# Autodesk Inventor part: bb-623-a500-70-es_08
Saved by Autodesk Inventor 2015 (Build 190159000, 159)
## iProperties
Created: 2022-04
Part Number: bb-623-a500-70-es_08
Checked By: TraceParts S.A.
Material: Generic
Catalog Web Link: www.traceparts.com
Document SubType Name: Modeling
Designer: TraceParts
Density: 1 g/cm^3
Appearance: Default
Company: TraceParts S.A.
Author: TraceParts
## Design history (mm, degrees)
feature "bb-623-a500-70-es_08.ipt"
body "Solid1"
